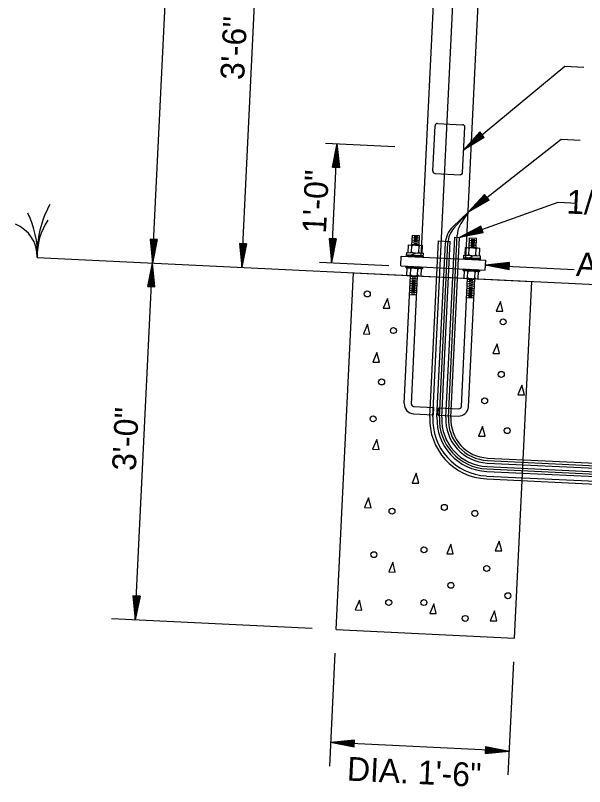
# Model space of a CAD drawing. Extents: x 661018 to 663325, y 642537 to 643074.
# Drawn here: x 661672.8 to 661753.3, y 642757.2 to 642866.3 of the extents above; entities that cross this region are included whole.
import ezdxf

# ---------------------------------------------------------------- set-up
doc = ezdxf.new("R2010")
doc.units = 0
doc.layers.add('R_Dimension', color=7, linetype='Continuous')

msp = doc.modelspace()

# ---------------------------------------------------------------- linework, layer by layer
at = {"layer": 'R_Dimension'}
for p, q in [((661692.17, 642831.3), (661697.2, 642934.95)), ((661730.16, 642832.15), (661733.3, 642896.77)), ((661736.47, 642831.84), (661739.61, 642896.46)), ((661704.79, 642830.69), (661707.65, 642889.58)), ((661731.8, 642809.54), (661735.4, 642883.54)), ((661736.17, 642847.32), (661750.47, 642859.14)), ((661750.47, 642859.14), (661753.16, 642859.01)), ((661731.8, 642844.33), (661732.12, 642850.72)), ((661732.47, 642851.04), (661736, 642850.87)), ((661736.01, 642844.12), (661736.32, 642850.52)), ((661738.44, 642849.86), (661736.17, 642847.32)), ((661738.49, 642849.79), (661736.6, 642847.68)), ((661738.55, 642849.73), (661737.05, 642848.05)), ((661738.6, 642849.66), (661737.48, 642848.41)), ((661738.92, 642849.28), (661737.48, 642848.41)), ((661738.66, 642849.6), (661737.92, 642848.77)), ((661738.87, 642849.34), (661737.92, 642848.77)), ((661738.71, 642849.53), (661738.35, 642849.13)), ((661738.81, 642849.41), (661738.35, 642849.13)), ((661739.08, 642849.08), (661738.44, 642849.86)), ((661716.61, 642848.27), (661726.41, 642847.79)), ((661717.47, 642831.36), (661718.29, 642848.19)), ((661717.62, 642844.85), (661718.29, 642848.19)), ((661718.63, 642844.8), (661718.29, 642848.19)), ((661739.08, 642849.08), (661736.17, 642847.32)), ((661739.03, 642849.14), (661736.6, 642847.68)), ((661736.79, 642838.49), (661749.97, 642848.81)), ((661738.98, 642849.21), (661737.05, 642848.05)), ((661749.97, 642848.81), (661752.66, 642848.68)), ((661717.7, 642844.84), (661718.26, 642847.63)), ((661718.55, 642844.8), (661718.26, 642847.63)), ((661717.79, 642844.84), (661718.23, 642847.05)), ((661717.87, 642844.84), (661718.21, 642846.49)), ((661718.38, 642844.81), (661718.21, 642846.49)), ((661718.46, 642844.81), (661718.23, 642847.05)), ((661717.96, 642844.83), (661718.18, 642845.92)), ((661718.05, 642844.83), (661718.15, 642845.35)), ((661718.2, 642844.82), (661718.15, 642845.35)), ((661718.29, 642844.82), (661718.18, 642845.92)), ((661717.62, 642844.85), (661718.63, 642844.8)), ((661732.12, 642843.97), (661735.66, 642843.8)), ((661739.12, 642840.98), (661736.79, 642838.49)), ((661739.17, 642840.91), (661737.23, 642838.84)), ((661739.22, 642840.85), (661737.69, 642839.2)), ((661739.27, 642840.78), (661738.13, 642839.55)), ((661739.33, 642840.71), (661738.57, 642839.9)), ((661739.38, 642840.65), (661739.01, 642840.25)), ((661739.48, 642840.52), (661739.01, 642840.25)), ((661739.75, 642840.19), (661739.12, 642840.98)), ((661735.59, 642834.92), (661749.53, 642839.9)), ((661739.75, 642840.19), (661736.79, 642838.49)), ((661739.69, 642840.25), (661737.23, 642838.84)), ((661739.64, 642840.32), (661737.69, 642839.2)), ((661739.59, 642840.39), (661738.13, 642839.55)), ((661739.53, 642840.46), (661738.57, 642839.9)), ((661749.53, 642839.9), (661752.23, 642839.77)), ((661736.79, 642838.49), (661734.63, 642836.44)), ((661736.79, 642838.49), (661734.77, 642836.22)), ((661736.79, 642838.49), (661735.78, 642836.89)), ((661738.6, 642836.53), (661735.59, 642834.92)), ((661738.62, 642836.45), (661736.12, 642835.11)), ((661738.65, 642836.37), (661736.67, 642835.31)), ((661738.68, 642836.29), (661737.2, 642835.49)), ((661738.71, 642836.21), (661737.73, 642835.69)), ((661738.94, 642835.58), (661738.6, 642836.53)), ((661728.85, 642833.84), (661728.92, 642835.25)), ((661728.92, 642835.25), (661729.93, 642835.2)), ((661729.16, 642835.07), (661729.67, 642835.04)), ((661729.86, 642833.79), (661729.93, 642835.2)), ((661734, 642809.44), (661735.26, 642835.25)), ((661738.94, 642835.58), (661735.59, 642834.92)), ((661738.91, 642835.66), (661736.12, 642835.11)), ((661738.88, 642835.74), (661736.67, 642835.31)), ((661738.85, 642835.82), (661737.2, 642835.49)), ((661738.82, 642835.9), (661737.73, 642835.69)), ((661738.74, 642836.13), (661738.26, 642835.88)), ((661738.79, 642835.98), (661738.26, 642835.88)), ((661691.83, 642834.69), (661692.17, 642831.3)), ((661692.84, 642834.64), (661691.83, 642834.69)), ((661691.91, 642834.69), (661692.2, 642831.86)), ((661692, 642834.68), (661692.22, 642832.44)), ((661692.08, 642834.68), (661692.25, 642833)), ((661692.17, 642834.67), (661692.28, 642833.57)), ((661692.84, 642834.64), (661692.17, 642831.3)), ((661692.75, 642834.65), (661692.2, 642831.86)), ((661692.67, 642834.65), (661692.22, 642832.44)), ((661692.25, 642834.67), (661692.31, 642834.13)), ((661692.58, 642834.65), (661692.25, 642833)), ((661692.5, 642834.66), (661692.28, 642833.57)), ((661692.41, 642834.66), (661692.31, 642834.13)), ((661704.45, 642834.08), (661704.79, 642830.69)), ((661705.46, 642834.03), (661704.45, 642834.08)), ((661704.53, 642834.07), (661704.82, 642831.25)), ((661704.62, 642834.07), (661704.84, 642831.83)), ((661704.7, 642834.07), (661704.87, 642832.39)), ((661704.79, 642834.06), (661704.9, 642832.96)), ((661705.46, 642834.03), (661704.79, 642830.69)), ((661705.37, 642834.03), (661704.82, 642831.25)), ((661705.29, 642834.04), (661704.84, 642831.83)), ((661704.87, 642834.06), (661704.93, 642833.52)), ((661705.2, 642834.04), (661704.87, 642832.39)), ((661705.12, 642834.04), (661704.9, 642832.96)), ((661705.03, 642834.05), (661704.93, 642833.52)), ((661717.13, 642834.75), (661717.47, 642831.36)), ((661718.14, 642834.7), (661717.13, 642834.75)), ((661717.21, 642834.75), (661717.5, 642831.92)), ((661717.3, 642834.74), (661717.53, 642832.5)), ((661717.38, 642834.74), (661717.55, 642833.06)), ((661717.47, 642834.74), (661717.58, 642833.63)), ((661718.14, 642834.7), (661717.47, 642831.36)), ((661718.06, 642834.71), (661717.5, 642831.92)), ((661717.97, 642834.71), (661717.53, 642832.5)), ((661717.89, 642834.72), (661717.55, 642833.06)), ((661717.56, 642834.73), (661717.61, 642834.2)), ((661717.8, 642834.72), (661717.58, 642833.63)), ((661717.71, 642834.72), (661717.61, 642834.2)), ((661728.87, 642834.28), (661729.88, 642834.23)), ((661728.89, 642834.6), (661729.9, 642834.55)), ((661728.9, 642834.92), (661729.91, 642834.87)), ((661729.12, 642834.09), (661729.62, 642834.07)), ((661729.13, 642834.42), (661729.64, 642834.39)), ((661729.15, 642834.74), (661729.65, 642834.72)), ((661731.38, 642809.56), (661732.59, 642834.42)), ((661732.39, 642809.52), (661733.59, 642834.16)), ((661732.59, 642834.42), (661734.27, 642834.34)), ((661732.73, 642809.5), (661733.92, 642834.14)), ((661733.06, 642809.48), (661734.27, 642834.34)), ((661733.65, 642809.45), (661734.89, 642834.96)), ((661734.35, 642809.42), (661735.59, 642834.92)), ((661734.89, 642834.96), (661735.59, 642834.92)), ((661736.93, 642833.45), (661736.99, 642834.85)), ((661736.96, 642834.21), (661737.97, 642834.16)), ((661736.98, 642834.53), (661737.99, 642834.48)), ((661736.99, 642834.85), (661738, 642834.8)), ((661737.21, 642834.03), (661737.71, 642834)), ((661737.22, 642834.35), (661737.73, 642834.33)), ((661737.24, 642834.67), (661737.74, 642834.65)), ((661737.94, 642833.4), (661738, 642834.8)), ((661728.29, 642832.81), (661728.35, 642833.87)), ((661728.35, 642833.87), (661730.36, 642833.77)), ((661728.8, 642832.78), (661728.85, 642833.84)), ((661728.86, 642833.95), (661729.86, 642833.9)), ((661729.81, 642832.73), (661729.86, 642833.79)), ((661730.31, 642832.71), (661730.36, 642833.77)), ((661736.37, 642832.41), (661736.42, 642833.48)), ((661736.42, 642833.48), (661738.44, 642833.38)), ((661736.87, 642832.39), (661736.93, 642833.45)), ((661736.93, 642833.56), (661737.94, 642833.51)), ((661736.95, 642833.88), (661737.96, 642833.83)), ((661737.19, 642833.7), (661737.7, 642833.68)), ((661737.88, 642832.34), (661737.94, 642833.4)), ((661738.39, 642832.32), (661738.44, 642833.38)), ((661675.86, 642832.09), (661853.7, 642823.46)), ((661727.27, 642830.89), (661727.34, 642832.29)), ((661727.34, 642832.29), (661739.29, 642831.71)), ((661728.1, 642832.25), (661728.13, 642832.81)), ((661728.1, 642832.36), (661728.23, 642832.47)), ((661728.11, 642832.48), (661730.46, 642832.36)), ((661728.11, 642832.25), (661728.35, 642832.46)), ((661728.13, 642832.81), (661730.48, 642832.7)), ((661728.23, 642832.25), (661728.46, 642832.46)), ((661728.35, 642832.24), (661728.58, 642832.45)), ((661728.47, 642832.23), (661728.7, 642832.45)), ((661728.59, 642832.23), (661728.78, 642832.4)), ((661728.7, 642832.22), (661728.77, 642832.28)), ((661728.77, 642832.27), (661728.95, 642832.43)), ((661728.78, 642832.44), (661729.39, 642832.74)), ((661728.78, 642832.39), (661728.84, 642832.44)), ((661728.84, 642832.22), (661729.07, 642832.43)), ((661728.96, 642832.21), (661729.19, 642832.42)), ((661729.08, 642832.2), (661729.31, 642832.42)), ((661729.2, 642832.2), (661729.43, 642832.41)), ((661729.31, 642832.19), (661729.55, 642832.41)), ((661729.43, 642832.19), (661729.67, 642832.4)), ((661729.55, 642832.18), (661729.79, 642832.39)), ((661729.67, 642832.18), (661729.79, 642832.28)), ((661729.78, 642832.25), (661729.93, 642832.39)), ((661729.79, 642832.37), (661729.81, 642832.39)), ((661729.82, 642832.17), (661730.05, 642832.38)), ((661729.93, 642832.16), (661730.17, 642832.38)), ((661730.05, 642832.16), (661730.16, 642832.26)), ((661730.16, 642832.16), (661730.38, 642832.37)), ((661730.17, 642832.28), (661730.26, 642832.37)), ((661730.27, 642832.15), (661730.46, 642832.32)), ((661730.39, 642832.14), (661730.46, 642832.2)), ((661730.45, 642832.14), (661730.48, 642832.7)), ((661736.17, 642831.86), (661736.2, 642832.42)), ((661736.19, 642832.08), (661738.54, 642831.97)), ((661736.2, 642832.42), (661738.56, 642832.31)), ((661736.2, 642831.86), (661736.43, 642832.07)), ((661736.22, 642831.99), (661736.32, 642832.08)), ((661736.32, 642831.85), (661736.48, 642832)), ((661736.44, 642831.85), (661736.47, 642831.88)), ((661736.47, 642831.91), (661736.64, 642832.06)), ((661736.48, 642832.03), (661736.52, 642832.07)), ((661736.52, 642831.84), (661736.75, 642832.06)), ((661736.64, 642831.84), (661736.86, 642832.04)), ((661736.76, 642831.83), (661736.85, 642831.92)), ((661736.85, 642831.89), (661737.02, 642832.04)), ((661736.86, 642832), (661736.9, 642832.05)), ((661736.91, 642831.82), (661737.14, 642832.04)), ((661736.96, 642832.05), (661737.53, 642832.35)), ((661737.03, 642831.82), (661737.26, 642832.03)), ((661737.15, 642831.81), (661737.38, 642832.03)), ((661737.26, 642831.81), (661737.5, 642832.02)), ((661737.38, 642831.8), (661737.62, 642832.01)), ((661737.5, 642831.79), (661737.74, 642832.01)), ((661737.62, 642831.79), (661737.86, 642832)), ((661737.74, 642831.78), (661737.86, 642831.89)), ((661737.86, 642831.87), (661738, 642832)), ((661737.87, 642831.99), (661737.88, 642832)), ((661737.88, 642831.78), (661738.11, 642831.99)), ((661738, 642831.77), (661738.23, 642831.98)), ((661738.12, 642831.76), (661738.35, 642831.98)), ((661738.24, 642831.76), (661738.47, 642831.97)), ((661738.35, 642831.75), (661738.5, 642831.88)), ((661738.53, 642831.74), (661738.56, 642832.31)), ((661689.72, 642780.82), (661692.17, 642831.3)), ((661691.5, 642827.96), (661692.17, 642831.3)), ((661691.59, 642827.96), (661692.14, 642830.74)), ((661692.43, 642827.91), (661692.14, 642830.74)), ((661692.51, 642827.91), (661692.17, 642831.3)), ((661715.79, 642831.44), (661725.59, 642830.97)), ((661727.27, 642830.89), (661739.22, 642830.31)), ((661728.02, 642830.62), (661728.03, 642830.85)), ((661728.02, 642830.74), (661728.14, 642830.84)), ((661728.03, 642830.62), (661728.26, 642830.84)), ((661728.15, 642830.62), (661728.38, 642830.83)), ((661728.26, 642830.61), (661728.5, 642830.83)), ((661728.38, 642830.61), (661728.62, 642830.82)), ((661728.5, 642830.6), (661728.7, 642830.78)), ((661728.69, 642830.64), (661728.88, 642830.81)), ((661728.7, 642830.76), (661728.76, 642830.81)), ((661728.76, 642830.59), (661729, 642830.8)), ((661728.88, 642830.58), (661729.11, 642830.8)), ((661729, 642830.58), (661729.23, 642830.79)), ((661729.12, 642830.57), (661729.35, 642830.79)), ((661729.24, 642830.57), (661729.47, 642830.78)), ((661729.36, 642830.56), (661729.59, 642830.77)), ((661729.47, 642830.55), (661729.71, 642830.77)), ((661729.7, 642830.54), (661729.94, 642830.76)), ((661729.71, 642830.66), (661729.82, 642830.76)), ((661729.82, 642830.54), (661730.06, 642830.75)), ((661729.94, 642830.53), (661730.17, 642830.75)), ((661730.06, 642830.53), (661730.29, 642830.74)), ((661730.18, 642830.52), (661730.38, 642830.71)), ((661730.37, 642830.51), (661730.39, 642830.73)), ((661738.47, 642831.75), (661738.52, 642831.79)), ((661739.22, 642830.31), (661739.29, 642831.71)), ((661742.64, 642831.35), (661739.25, 642831.01)), ((661739.25, 642831.01), (661751.78, 642830.4)), ((661742.59, 642830.34), (661739.25, 642831.01)), ((661742.64, 642831.26), (661739.82, 642830.98)), ((661742.6, 642830.42), (661739.82, 642830.98)), ((661742.63, 642831.18), (661740.39, 642830.95)), ((661742.6, 642830.51), (661740.39, 642830.95)), ((661742.63, 642831.09), (661740.95, 642830.92)), ((661742.61, 642830.59), (661740.95, 642830.92)), ((661742.63, 642831.01), (661741.52, 642830.9)), ((661742.61, 642830.68), (661741.52, 642830.9)), ((661742.62, 642830.92), (661742.09, 642830.87)), ((661742.61, 642830.76), (661742.09, 642830.87)), ((661742.59, 642830.34), (661742.64, 642831.35)), ((661691.67, 642827.95), (661692.11, 642830.16)), ((661692.34, 642827.92), (661692.11, 642830.16)), ((661718.11, 642779.44), (661720.56, 642829.92)), ((661720.56, 642829.92), (661745.8, 642828.7)), ((661728.02, 642830.62), (661730.37, 642830.51)), ((661728.14, 642829.55), (661728.19, 642830.62)), ((661728.62, 642830.6), (661728.7, 642830.66)), ((661728.64, 642829.53), (661728.69, 642830.59)), ((661729.59, 642830.55), (661729.71, 642830.65)), ((661729.65, 642829.48), (661729.7, 642830.54)), ((661730.15, 642829.46), (661730.21, 642830.52)), ((661730.3, 642830.51), (661730.38, 642830.59)), ((661736.1, 642830.23), (661736.11, 642830.46)), ((661736.1, 642830.23), (661738.45, 642830.12)), ((661736.11, 642830.45), (661736.12, 642830.46)), ((661736.16, 642830.38), (661736.24, 642830.45)), ((661736.21, 642830.31), (661736.36, 642830.44)), ((661736.21, 642829.16), (661736.26, 642830.22)), ((661736.25, 642830.24), (661736.47, 642830.44)), ((661736.36, 642830.22), (661736.59, 642830.43)), ((661736.48, 642830.21), (661736.71, 642830.43)), ((661736.6, 642830.21), (661736.78, 642830.37)), ((661736.71, 642830.2), (661736.77, 642830.25)), ((661736.72, 642829.14), (661736.77, 642830.2)), ((661736.77, 642830.25), (661736.96, 642830.42)), ((661736.78, 642830.36), (661736.84, 642830.42)), ((661736.84, 642830.2), (661737.08, 642830.41)), ((661736.96, 642830.19), (661737.2, 642830.4)), ((661737.08, 642830.18), (661737.32, 642830.4)), ((661737.2, 642830.18), (661737.43, 642830.39)), ((661737.32, 642830.17), (661737.55, 642830.39)), ((661737.44, 642830.17), (661737.67, 642830.38)), ((661737.56, 642830.16), (661737.79, 642830.37)), ((661737.68, 642830.16), (661737.78, 642830.25)), ((661737.73, 642829.09), (661737.78, 642830.15)), ((661737.78, 642830.25), (661737.91, 642830.37)), ((661737.79, 642830.37), (661737.79, 642830.38)), ((661737.79, 642830.15), (661738.03, 642830.36)), ((661737.91, 642830.14), (661738.15, 642830.36)), ((661738.03, 642830.14), (661738.27, 642830.35)), ((661738.15, 642830.13), (661738.39, 642830.35)), ((661738.23, 642829.06), (661738.28, 642830.13)), ((661738.27, 642830.13), (661738.32, 642830.18)), ((661738.45, 642830.12), (661738.46, 642830.34)), ((661691.76, 642827.95), (661692.09, 642829.6)), ((661691.84, 642827.94), (661692.06, 642829.03)), ((661692.17, 642827.93), (661692.06, 642829.03)), ((661692.26, 642827.92), (661692.09, 642829.6)), ((661727.76, 642811.41), (661728.64, 642829.53)), ((661728.14, 642829.55), (661730.15, 642829.46)), ((661728.6, 642828.77), (661729.61, 642828.73)), ((661728.62, 642829.1), (661729.63, 642829.05)), ((661728.64, 642829.42), (661729.64, 642829.37)), ((661728.77, 642811.35), (661729.65, 642829.48)), ((661728.85, 642828.59), (661729.35, 642828.57)), ((661728.86, 642828.92), (661729.37, 642828.89)), ((661728.88, 642829.24), (661729.38, 642829.22)), ((661735.84, 642811), (661736.72, 642829.14)), ((661736.21, 642829.16), (661738.23, 642829.06)), ((661736.7, 642828.71), (661737.71, 642828.66)), ((661736.71, 642829.03), (661737.72, 642828.98)), ((661736.85, 642810.97), (661737.73, 642829.09)), ((661736.94, 642828.53), (661737.45, 642828.5)), ((661736.96, 642828.85), (661737.46, 642828.82)), ((661743.35, 642778.22), (661745.8, 642828.7)), ((661691.5, 642827.96), (661692.51, 642827.91)), ((661691.93, 642827.94), (661692.03, 642828.47)), ((661692.08, 642827.93), (661692.03, 642828.47)), ((661728.54, 642827.48), (661729.55, 642827.43)), ((661728.56, 642827.8), (661729.57, 642827.75)), ((661728.57, 642828.13), (661729.58, 642828.08)), ((661728.59, 642828.45), (661729.6, 642828.4)), ((661728.8, 642827.62), (661729.31, 642827.6)), ((661728.82, 642827.95), (661729.32, 642827.92)), ((661728.83, 642828.27), (661729.34, 642828.25)), ((661736.65, 642827.74), (661737.66, 642827.69)), ((661736.66, 642828.06), (661737.67, 642828.01)), ((661736.68, 642828.38), (661737.69, 642828.33)), ((661736.89, 642827.55), (661737.4, 642827.53)), ((661736.91, 642827.88), (661737.41, 642827.85)), ((661736.92, 642828.2), (661737.43, 642828.18)), ((661728.51, 642826.83), (661729.52, 642826.78)), ((661728.53, 642827.16), (661729.53, 642827.11)), ((661728.77, 642826.98), (661729.27, 642826.95)), ((661728.79, 642827.3), (661729.29, 642827.28)), ((661736.59, 642826.44), (661737.6, 642826.39)), ((661736.6, 642826.76), (661737.61, 642826.72)), ((661736.62, 642827.09), (661737.63, 642827.04)), ((661736.63, 642827.41), (661737.64, 642827.36)), ((661736.85, 642826.58), (661737.35, 642826.56)), ((661736.86, 642826.91), (661737.37, 642826.88)), ((661736.88, 642827.23), (661737.38, 642827.21)), ((661729.09, 642810.99), (661731.95, 642810.85)), ((661731.9, 642809.8), (661731.95, 642810.85)), ((661732.57, 642809.77), (661732.62, 642810.82)), ((661732.62, 642810.82), (661735.48, 642810.68)), ((661729.09, 642809.94), (661731.9, 642809.8)), ((661732.57, 642809.77), (661735.38, 642809.63)), ((661739.53, 642803.7), (661822.77, 642799.66)), ((661739.47, 642802.5), (661822.71, 642798.45)), ((661739.5, 642803), (661822.74, 642798.96)), ((661739.51, 642803.35), (661821.92, 642799.35)), ((661739.44, 642801.82), (661824.9, 642797.67)), ((661739.45, 642802.16), (661827.36, 642797.89)), ((661739.39, 642800.74), (661822.63, 642796.7)), ((661739.41, 642801.16), (661822.65, 642797.12)), ((661689.38, 642784.21), (661689.72, 642780.82)), ((661690.39, 642784.16), (661689.38, 642784.21)), ((661689.46, 642784.21), (661689.75, 642781.38)), ((661689.55, 642784.2), (661689.77, 642781.96)), ((661689.63, 642784.2), (661689.8, 642782.52)), ((661689.72, 642784.19), (661689.83, 642783.09)), ((661690.39, 642784.16), (661689.72, 642780.82)), ((661690.3, 642784.17), (661689.75, 642781.38)), ((661690.22, 642784.17), (661689.77, 642781.96)), ((661689.8, 642784.19), (661689.86, 642783.65)), ((661690.13, 642784.17), (661689.8, 642782.52)), ((661690.04, 642784.18), (661689.83, 642783.09)), ((661689.96, 642784.18), (661689.86, 642783.65)), ((661686.35, 642780.98), (661714.75, 642779.61)), ((661718.11, 642779.44), (661743.35, 642778.22)), ((661717.95, 642776.08), (661717.17, 642760.09)), ((661743.19, 642774.85), (661742.41, 642758.87)), ((661720.73, 642763.8), (661717.34, 642763.46)), ((661742.58, 642762.23), (661717.34, 642763.46)), ((661720.68, 642762.79), (661717.34, 642763.46)), ((661720.72, 642763.71), (661717.9, 642763.43)), ((661720.68, 642762.87), (661717.9, 642763.43)), ((661720.72, 642763.63), (661718.48, 642763.4)), ((661720.69, 642762.96), (661718.48, 642763.4)), ((661720.71, 642763.54), (661719.04, 642763.37)), ((661720.69, 642763.04), (661719.04, 642763.37)), ((661720.71, 642763.46), (661719.61, 642763.35)), ((661720.69, 642763.13), (661719.61, 642763.35)), ((661720.71, 642763.37), (661720.17, 642763.32)), ((661720.7, 642763.21), (661720.17, 642763.32)), ((661720.68, 642762.79), (661720.73, 642763.8)), ((661739.24, 642762.9), (661739.19, 642761.89)), ((661739.19, 642762.06), (661741.43, 642762.29)), ((661739.19, 642761.97), (661742.01, 642762.26)), ((661739.19, 642761.89), (661742.58, 642762.23)), ((661739.2, 642762.23), (661740.3, 642762.34)), ((661739.2, 642762.14), (661740.87, 642762.31)), ((661739.21, 642762.47), (661739.74, 642762.37)), ((661739.21, 642762.32), (661739.74, 642762.37)), ((661739.22, 642762.65), (661740.87, 642762.31)), ((661739.22, 642762.56), (661740.3, 642762.34)), ((661739.23, 642762.82), (661742.01, 642762.26)), ((661739.23, 642762.73), (661741.43, 642762.29)), ((661739.24, 642762.9), (661742.58, 642762.23))]:
    msp.add_line(p, q, dxfattribs=at)
for points in [[(661725.37, 642826.27), (661724.8, 642824.9), (661725.72, 642824.89), (661725.37, 642826.27)], [(661741.35, 642825.87), (661740.77, 642824.5), (661741.7, 642824.49), (661741.35, 642825.87)], [(661722.56, 642822.63), (661721.98, 642821.26), (661722.91, 642821.25), (661722.56, 642822.63)], [(661740.89, 642819.86), (661740.31, 642818.49), (661741.24, 642818.48), (661740.89, 642819.86)], [(661723.9, 642818.66), (661723.32, 642817.29), (661724.25, 642817.28), (661723.9, 642818.66)], [(661744.4, 642814.01), (661743.83, 642812.64), (661744.75, 642812.63), (661744.4, 642814.01)], [(661738.84, 642808.18), (661738.27, 642806.8), (661739.19, 642806.8), (661738.84, 642808.18)], [(661723.86, 642806.31), (661723.29, 642804.94), (661724.22, 642804.93), (661723.86, 642806.31)], [(661729.45, 642801.54), (661728.87, 642800.17), (661729.8, 642800.16), (661729.45, 642801.54)], [(661722.71, 642798.06), (661722.13, 642796.69), (661723.06, 642796.68), (661722.71, 642798.06)], [(661734.35, 642791.51), (661733.77, 642790.14), (661734.7, 642790.14), (661734.35, 642791.51)], [(661741.2, 642791.94), (661740.63, 642790.56), (661741.55, 642790.56), (661741.2, 642791.94)], [(661726.14, 642788.95), (661725.57, 642787.58), (661726.49, 642787.57), (661726.14, 642788.95)], [(661721.41, 642783.58), (661720.84, 642782.21), (661721.77, 642782.2), (661721.41, 642783.58)], [(661731.94, 642783.07), (661731.37, 642781.69), (661732.29, 642781.69), (661731.94, 642783.07)], [(661740.51, 642782.06), (661739.93, 642780.69), (661740.86, 642780.68), (661740.51, 642782.06)]]:
    msp.add_lwpolyline(points, dxfattribs=at)
for centre in [(661722.53, 642826.92), (661741.74, 642822.97), (661726.23, 642821.74), (661741.48, 642815.54), (661724.56, 642814.47), (661739.13, 642811.79), (661723.36, 642809.25), (661742.32, 642807.58), (661733.43, 642796.72), (661726.03, 642796.18), (661737.75, 642795.87), (661723.46, 642790.03), (661730.55, 642790.72), (661739.42, 642788.08), (661734.35, 642785.69), (661742.41, 642784.22), (661725.56, 642783.26), (661730.54, 642783.25), (661736.38, 642781.01)]:
    msp.add_circle(centre, 0.421, dxfattribs=at)
for centre, radius, start, end in [((661732.45, 642850.71), 0.337, 87.2199, 177.2199), ((661735.99, 642850.53), 0.337, 357.2199, 87.2199), ((661732.14, 642844.31), 0.337, 177.2199, 267.2199), ((661735.67, 642844.14), 0.337, 267.2199, 357.2199), ((661690.03, 642832.65), 14.19, 150.8235, 182.237), ((661662.98, 642832.63), 12.89, 357.6269, 26.4493), ((661684.82, 642832.39), 8.97, 146.3648, 181.8916), ((661670.98, 642832.24), 4.88, 358.2316, 68.4339), ((661736.95, 642833.99), 3.37, 133.5429, 177.2199), ((661737.29, 642833.98), 3.37, 138.338, 177.2199), ((661738.62, 642835.08), 3.37, 147.6268, 177.2199), ((661728.64, 642832.96), 0.168, 267.2199, 357.2199), ((661728.67, 642833.68), 0.168, 357.2199, 87.2199), ((661728.97, 642832.94), 0.168, 177.2199, 267.2199), ((661729.01, 642833.67), 0.168, 87.2199, 177.2199), ((661729.65, 642832.91), 0.168, 267.2199, 357.2199), ((661729.68, 642833.63), 0.168, 357.2199, 87.2199), ((661729.98, 642832.89), 0.168, 177.2199, 267.2199), ((661730.02, 642833.62), 0.168, 87.2199, 177.2199), ((661736.75, 642833.29), 0.168, 357.2199, 87.2199), ((661737.09, 642833.28), 0.168, 87.2199, 177.2199), ((661737.76, 642833.24), 0.168, 357.2199, 87.2199), ((661738.1, 642833.23), 0.168, 87.2199, 177.2199), ((661736.71, 642832.57), 0.168, 267.2199, 357.2199), ((661737.05, 642832.55), 0.168, 177.2199, 267.2199), ((661737.72, 642832.52), 0.168, 267.2199, 357.2199), ((661738.06, 642832.5), 0.168, 177.2199, 267.2199), ((661728.48, 642829.71), 0.168, 267.2199, 357.2199), ((661728.52, 642830.43), 0.168, 357.2199, 87.2199), ((661728.82, 642829.69), 0.168, 177.2199, 267.2199), ((661728.85, 642830.42), 0.168, 87.2199, 177.2199), ((661729.49, 642829.66), 0.168, 267.2199, 357.2199), ((661729.53, 642830.38), 0.168, 357.2199, 87.2199), ((661729.83, 642829.64), 0.168, 177.2199, 267.2199), ((661729.86, 642830.37), 0.168, 87.2199, 177.2199), ((661736.59, 642830.04), 0.168, 357.2199, 87.2199), ((661736.93, 642830.02), 0.168, 87.2199, 177.2199), ((661737.6, 642829.99), 0.168, 357.2199, 87.2199), ((661737.94, 642829.97), 0.168, 87.2199, 177.2199), ((661736.56, 642829.31), 0.168, 267.2199, 357.2199), ((661736.89, 642829.3), 0.168, 177.2199, 267.2199), ((661737.57, 642829.26), 0.168, 267.2199, 357.2199), ((661737.9, 642829.25), 0.168, 177.2199, 267.2199), ((661729.16, 642811.34), 1.4, 177.2199, 267.2199), ((661729.11, 642811.33), 0.337, 177.2199, 267.2199), ((661735.44, 642811.04), 1.4, 267.2199, 357.2199), ((661735.5, 642811.02), 0.337, 267.2199, 357.2199), ((661739.79, 642809.16), 8.42, 177.2199, 267.2199), ((661739.79, 642809.16), 8, 177.2199, 267.2199), ((661739.76, 642809.19), 7.38, 177.5199, 267.5199), ((661739.76, 642809.19), 7.04, 177.5199, 267.5199), ((661739.76, 642809.19), 6.7, 177.5199, 267.5199), ((661739.8, 642809.15), 6.16, 177.1546, 267.1546), ((661739.8, 642809.15), 5.8, 177.1462, 267.1462), ((661739.8, 642809.15), 5.45, 177.1462, 267.1462)]:
    msp.add_arc(centre, radius, start, end, dxfattribs=at)

# ---------------------------------------------------------------- texts
for s, height, rotation, p in [('3\'-6"', 3.369, 87.2199, (661705.11, 642857.15)), ('1\'-0"', 3.369, 87.2199, (661716.68, 642835.43)), (' 1/2" NMC ', 3.369, 357.2199, (661749.4, 642838.38)), ('ANCHOR BASE', 3.3692, 357.2199, (661752, 642829.47)), ('3\'-0"', 3.369, 87.2199, (661689.79, 642801.84)), ('DIA. 1\'-6"', 3.369, 357.2199, (661719.61, 642758.07))]:
    msp.add_text(s, height=height, rotation=rotation, dxfattribs=at).set_placement(p)

doc.saveas('drawing.dxf')
